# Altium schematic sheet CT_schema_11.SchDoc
size 146 x 119 mm
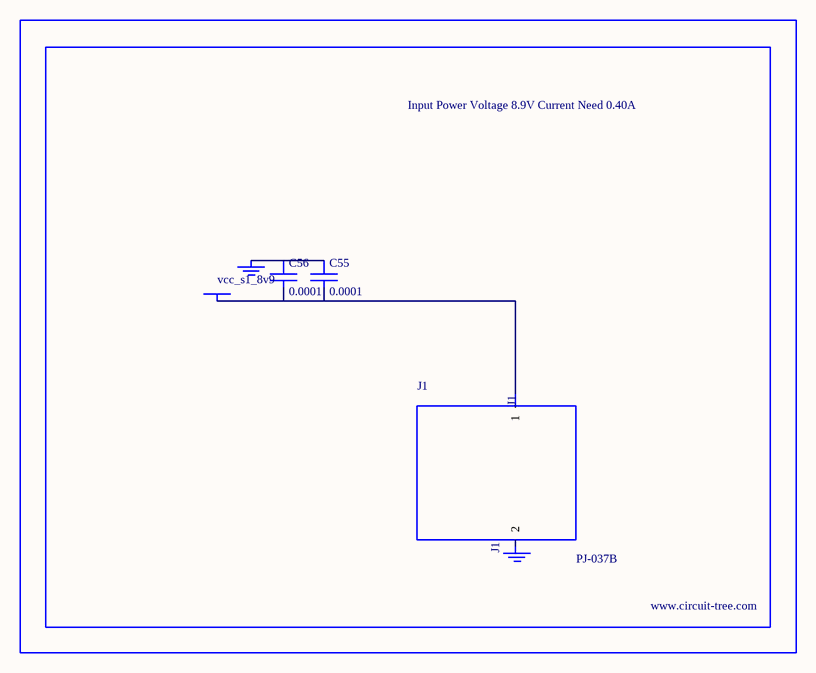
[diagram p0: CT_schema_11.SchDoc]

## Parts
BORDER10  (no value)
C55  0.0001  [EXV-9H]
C56  0.0001  [EXV-9H]
GND_INSTANCE_10_0  (no value)
GND_INSTANCE_10_1  (no value)
J1  PJ-037B  [PJ-037B_PACKAGE]
POWER_INSTANCE_10_0  vcc_s1_8v9

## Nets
NetC55_1: C55.1 C56.1 GND_INSTANCE_10_0.0(GND)
NetC55_2: C55.2 C56.2 J1.1 POWER_INSTANCE_10_0.0(PWR)

Not connected (* = marked no-connect by the designer): GND_INSTANCE_10_1 0(GND); J1 2

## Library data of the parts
BORDER10 = BORDER_PAGE10
C55 C56 = EDK107M035A9HAA
GND_INSTANCE_10_0 GND_INSTANCE_10_1 = GND
POWER_INSTANCE_10_0 = PWR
